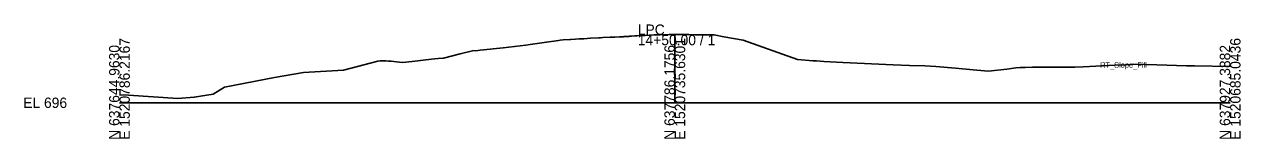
# Model space of a CAD drawing. Extents: x -26 to 303, y -10 to 4521.
# Drawn here: x -25.7 to 302.8, y 4490.3 to 4521.2 of the extents above; entities that cross this region are included whole.
import ezdxf

# ---------------------------------------------------------------- set-up
doc = ezdxf.new("R2010")
doc.units = 0
for name, color, linetype in [('Default', 7, 'Continuous'), ('Exist Cross Section Cell', 7, 'Continuous'), ('Exist XS Ground Line', 7, 'Continuous'), ('Prop XS Shear Point Element', 7, 'Continuous')]:
    doc.layers.add(name, color=color, linetype=linetype)

msp = doc.modelspace()

# ---------------------------------------------------------------- linework, layer by layer
at = {"layer": 'Exist Cross Section Cell'}
for p, q in [((150, 4500), (150, 4518.34)), ((0, 4500), (150, 4500)), ((150, 4500), (300, 4500))]:
    msp.add_line(p, q, dxfattribs=at)
at = {"layer": 'Exist XS Ground Line'}
msp.add_lwpolyline([(0, 4502.13), (2.48, 4502.04), (15.75, 4501.11), (20.2, 4501.47), (25.33, 4502.35), (28.33, 4504.23), (41.84, 4506.8), (49.75, 4508.13), (60.49, 4508.82), (69.81, 4511.23), (70.4, 4511.32), (71.96, 4511.35), (72.66, 4511.27), (73.4, 4511.2), (74.86, 4511.05), (76.41, 4510.9), (79.09, 4511.13), (84.32, 4511.77), (86.06, 4511.94), (87.49, 4512.07), (92.03, 4513.24), (95.35, 4514.07), (95.43, 4514.09), (96.27, 4514.02), (97.47, 4514.18), (103.67, 4514.82), (109.74, 4515.58), (110.91, 4515.7), (114.73, 4516.29), (118.61, 4516.86), (119.01, 4516.9), (119.86, 4516.97), (121.71, 4517.08), (121.94, 4517.1), (123.16, 4517.17), (124.21, 4517.23), (124.58, 4517.26), (125.39, 4517.31), (127.24, 4517.43), (129.52, 4517.54), (129.89, 4517.56), (130.56, 4517.59), (132.54, 4517.69), (133.79, 4517.74), (135.08, 4517.79), (136.05, 4517.85), (136.36, 4517.87), (136.88, 4517.9), (137.05, 4517.91), (137.26, 4517.92), (137.39, 4517.93), (137.61, 4517.94), (137.85, 4517.96), (138.06, 4517.98), (138.21, 4517.99), (138.32, 4517.99), (139.17, 4518.05), (139.44, 4518.07), (139.66, 4518.08), (139.84, 4518.09), (140.53, 4518.13), (141.96, 4518.19), (143.18, 4518.26), (144.4, 4518.31), (144.55, 4518.32), (145.7, 4518.33), (145.83, 4518.33), (146.09, 4518.34), (148.47, 4518.4), (150, 4518.41), (150.21, 4518.41), (151.12, 4518.42), (152.75, 4518.41), (153.77, 4518.4), (155.46, 4518.39), (156.43, 4518.38), (158.15, 4518.39), (158.91, 4518.39), (159.13, 4518.38), (159.31, 4518.37), (160.36, 4518.35), (160.67, 4518.33), (163.2, 4517.83), (168.46, 4516.94), (183.1, 4511.71), (183.15, 4511.69), (183.21, 4511.69), (187.29, 4511.33), (188.3, 4511.28), (190.23, 4511.14), (195.35, 4510.87), (209, 4510.23), (213.39, 4510.09), (217.51, 4510), (220.51, 4509.8), (225.79, 4509.36), (227.72, 4509.19), (228.7, 4509.06), (231.55, 4508.77), (234.75, 4508.57), (239.67, 4509.1), (242.07, 4509.41), (243.32, 4509.49), (243.95, 4509.54), (244.59, 4509.56), (246.65, 4509.61), (248.29, 4509.63), (249.34, 4509.61), (256.67, 4509.6), (258.07, 4509.58), (260.29, 4509.7), (268.87, 4510.12), (271.93, 4510.26), (273.92, 4510.39), (280.22, 4510.24), (288.17, 4510.01), (290.39, 4509.99), (300, 4509.78)], dxfattribs=at)

# ---------------------------------------------------------------- texts
at = {"layer": 'Default'}
msp.add_text('-', height=0.0001, dxfattribs=at).set_placement((0, 4500))
at = {"layer": 'Exist Cross Section Cell'}
for s, p in [('LPC', (140, 4518.34)), ('14+50.00 / 1', (140, 4515.54)), ('EL 696', (-26, 4498.6))]:
    msp.add_text(s, height=2.8, dxfattribs=at).set_placement(p)
for s, p in [('N 637644.9630', (0, 4490)), ('E 1520786.2167', (2.8, 4490)), ('N 637786.1756', (150, 4490)), ('E 1520735.6301', (152.8, 4490)), ('N 637927.3882', (300, 4490)), ('E 1520685.0436', (302.8, 4490))]:
    msp.add_text(s, height=2.8, rotation=90, dxfattribs=at).set_placement(p)
at = {"layer": 'Prop XS Shear Point Element'}
msp.add_text('RT_Slope_Fill', height=1.5, dxfattribs=at).set_placement((264.87, 4509.45))

doc.saveas('drawing.dxf')
